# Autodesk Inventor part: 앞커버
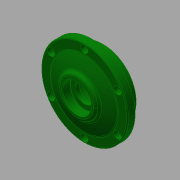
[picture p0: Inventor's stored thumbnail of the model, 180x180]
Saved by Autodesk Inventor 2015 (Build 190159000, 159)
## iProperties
Created: 2016-05
Part Number: 앞커버
Document SubType Name: Modeling
Designer: mduedu
Density: 2.71 g/cm^3
Material: 알루미늄 6061
Appearance: 진녹색
Author: mduedu
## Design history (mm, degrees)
sketch "스케치1"
  geometry: C1 r 35 at (0, 0); C2 r 45 at (0, 0); 1 further point
  constraints: 2 centre point, 2 coincident
  dimensions: "d33" = 90 diameter of C2; "d34" = 70 diameter of C1
extrude "돌출1" new body sketch "스케치1" distance "d0" = 8; taper "d1" = 0 deg
extrude "돌출2" join sketch "스케치1" distance "d2" = 8; taper "d3" = 0 deg; dims "d35" = 12, "d36" = 0
sketch "스케치5"
  geometry: L1 (-45, 8)-(45, 8) reference; L2 (0, 0)-(0, 15); L3 (-45, 0)-(45, 0) reference; L4 (35, 8)-(0, 8); A1 r 91 centre (0, -76) between (35, 8) and (0, 15)
  constraints: 4 end point, 3 point on line, 2 point on circle, 1 centre point, 1 midpoint, 1 perpendicular
  dimensions: "d37" = 35 distance from line of L2 L4.start; "d39" = 7 distance from line of L1 L2.end
revolve "회전2" sketch "스케치5" stored, may be unused: angle "d40" = 90 deg
node "작업 평면1"
sketch "스케치6"
  geometry: C1 r 20 at (0, 0); 1 further point
  constraints: 1 centre point, 1 coincident
  dimensions: "d42" = 40 diameter of C1
extrude "돌출4" join sketch "스케치6" stored distance "d43" = 10; taper "d44" = 0 deg
sketch "스케치4"
  geometry: L1 (0, -12)-(0, 16); L2 (-20, -12)-(-20, 0); L3 (-20, 0)-(-15, 0); L4 (-15, 0)-(-15, 3); L5 (-15, 3)-(-10, 3); L6 (-10, 3)-(-10, 7.5); L7 (-10, 7.5)-(-15, 7.5); L8 (-15, 7.5)-(-15, 16); L9 (35, -12)-(-35, -12) reference; L10 (-20, 16)-(20, 16) reference; 1 further point
  constraints: 16 end point, 6 parallel, 3 point on line, 2 midpoint, 1 perpendicular, 1 vertical
  dimensions: "d15" = 40 diameter of L2 L1; "d16" = 30 diameter of L8 L1; "d18" = 12 distance of L2.start L2.end; "d19" = 3 distance of L3.end L4.end; "d20" = 30 diameter of L4 L1; "d21" = 20 diameter of L6 L1; "d45" = 8.5 distance of L7.end L8.end
revolve "회전1" sketch "스케치4" stored, may be unused: angle "d22" = 90 deg
fillet "모깎기2" dims "d23" = 3
fillet "모깎기3" dims "d24" = 0.3
chamfer "모따기2" distance "d46" = 1; stored, may be unused: second distance "d47" = 2, angle "d48" = 45 deg
fillet "모깎기4" dims "d49" = 3
fillet "모깎기5" dims "d50" = 3
fillet "모깎기6" dims "d51" = 1
sketch "스케치7" dims "d52" = 80
  geometry: C1 r 35.595 at (0, 0) reference; C2 r 44 at (0, 0) reference; 7 further points
  constraints: 2 vertical alignment, 1 coincident, 9 other
  dimensions: "d55" = 360 deg dimension on C1.centre point (0, 40) (derived)
sketch "스케치8"
  geometry: 6 further points
  constraints: 6 other
hole "구멍2" sketch "스케치8" at (-34.641, 20), (-34.641, -20), (0, -40), (34.641, -20), (34.641, 20), (0, 40) diameter "d57" = 4.5; stored, may be unused: countersink angle "d61" = 90 deg, drill point angle "d63" = 0 deg; dims "d58" = 6, "d59" = 8, "d60" = 4.6, "d62" = 8
chamfer "모따기3" distance "d64" = 0.8; stored, may be unused: second distance "d65" = 2, angle "d66" = 30 deg
node "솔리드1"
other parameters: "d41" = 8
